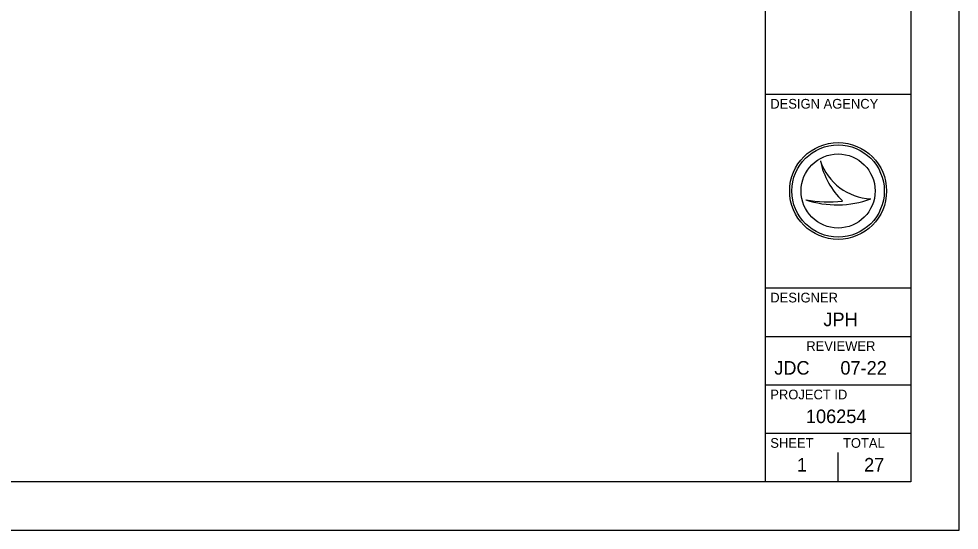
# Model space of a CAD drawing. Extents: x 39.8 to 73.8, y 13 to 35.
# Drawn here: x 64.06 to 73.76, y 12.96 to 18.24 of the extents above; entities that cross this region are included whole.
import ezdxf

# ---------------------------------------------------------------- set-up
doc = ezdxf.new("R2010")
doc.units = 0
for name, color, linetype in [('SH_Border', 7, 'Continuous'), ('SH_Cut_Line', 7, 'Continuous'), ('SH_Data', 7, 'Continuous')]:
    doc.layers.add(name, color=color, linetype=linetype)

msp = doc.modelspace()

# ---------------------------------------------------------------- linework, layer by layer
at = {"layer": 'SH_Border'}
for p, q in [((71.763, 13.465), (71.763, 34.465)), ((71.763, 17.465), (73.263, 17.465)), ((71.763, 15.465), (73.263, 15.465)), ((71.763, 14.965), (73.263, 14.965)), ((71.763, 14.465), (73.263, 14.465)), ((71.763, 13.965), (73.263, 13.965))]:
    msp.add_line(p, q, dxfattribs=at)
msp.add_lwpolyline([(41.263, 34.465), (73.263, 34.465), (73.263, 13.465), (41.263, 13.465)], close=True, dxfattribs=at)
at = {"layer": 'SH_Cut_Line'}
msp.add_lwpolyline([(39.763, 12.965), (73.763, 12.965), (73.763, 34.965), (39.763, 34.965)], close=True, dxfattribs=at)
at = {"layer": 'SH_Data'}
for p, q in [((72.3304, 16.7745), (72.3304, 16.7745)), ((72.513, 16.465), (72.513, 16.465)), ((72.1802, 16.3745), (72.1801, 16.3745)), ((72.8503, 16.3835), (72.8503, 16.3835)), ((72.513, 13.465), (72.513, 13.765)), ((72.138, 13.64), (72.138, 13.64))]:
    msp.add_line(p, q, dxfattribs=at)
for radius in [0.5, 0.4768, 0.4768, 0.3822]:
    msp.add_circle((72.513, 16.465), radius, dxfattribs=at)
for centre, radius, start, end in [((72.8789, 16.9626), 0.5798, 198.92567, 198.93195), ((73.1097, 16.935), 0.7956, 191.63793, 191.64215), ((72.8789, 16.9626), 0.5798, 198.93195, 267.16574), ((73.1097, 16.935), 0.7956, 191.64215, 226.09467), ((72.5024, 17.335), 1.0131, 251.45274, 251.45764), ((72.5024, 17.335), 1.0131, 251.45764, 290.08324), ((72.411, 17.6193), 1.2661, 259.49639, 259.49952), ((72.411, 17.6193), 1.2661, 259.49952, 276.66723)]:
    msp.add_arc(centre, radius, start, end, dxfattribs=at)

# ---------------------------------------------------------------- texts
for s, height, p in [('DESIGN AGENCY', 0.1, (71.813, 17.315)), ('DESIGNER', 0.1, (71.813, 15.315)), ('JPH', 0.14, (72.3613, 15.07)), ('REVIEWER', 0.1, (72.1848, 14.815)), ('JDC', 0.14, (71.8542, 14.57)), ('07-22', 0.14, (72.5368, 14.57)), ('PROJECT ID', 0.1, (71.813, 14.315)), ('106254', 0.14, (72.1809, 14.07)), ('SHEET', 0.1, (71.813, 13.815)), ('TOTAL', 0.1, (72.563, 13.815)), ('1', 0.14, (72.0881, 13.57)), ('27', 0.14, (72.7813, 13.57))]:
    msp.add_text(s, height=height, dxfattribs=at).set_placement(p)

doc.saveas('drawing.dxf')
